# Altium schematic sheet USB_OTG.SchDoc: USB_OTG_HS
size A4; DocumentNumber: MB1165; Revision: C.1; SheetNumber: 8; SheetTotal: 17; Project: STM32469I-EVAL
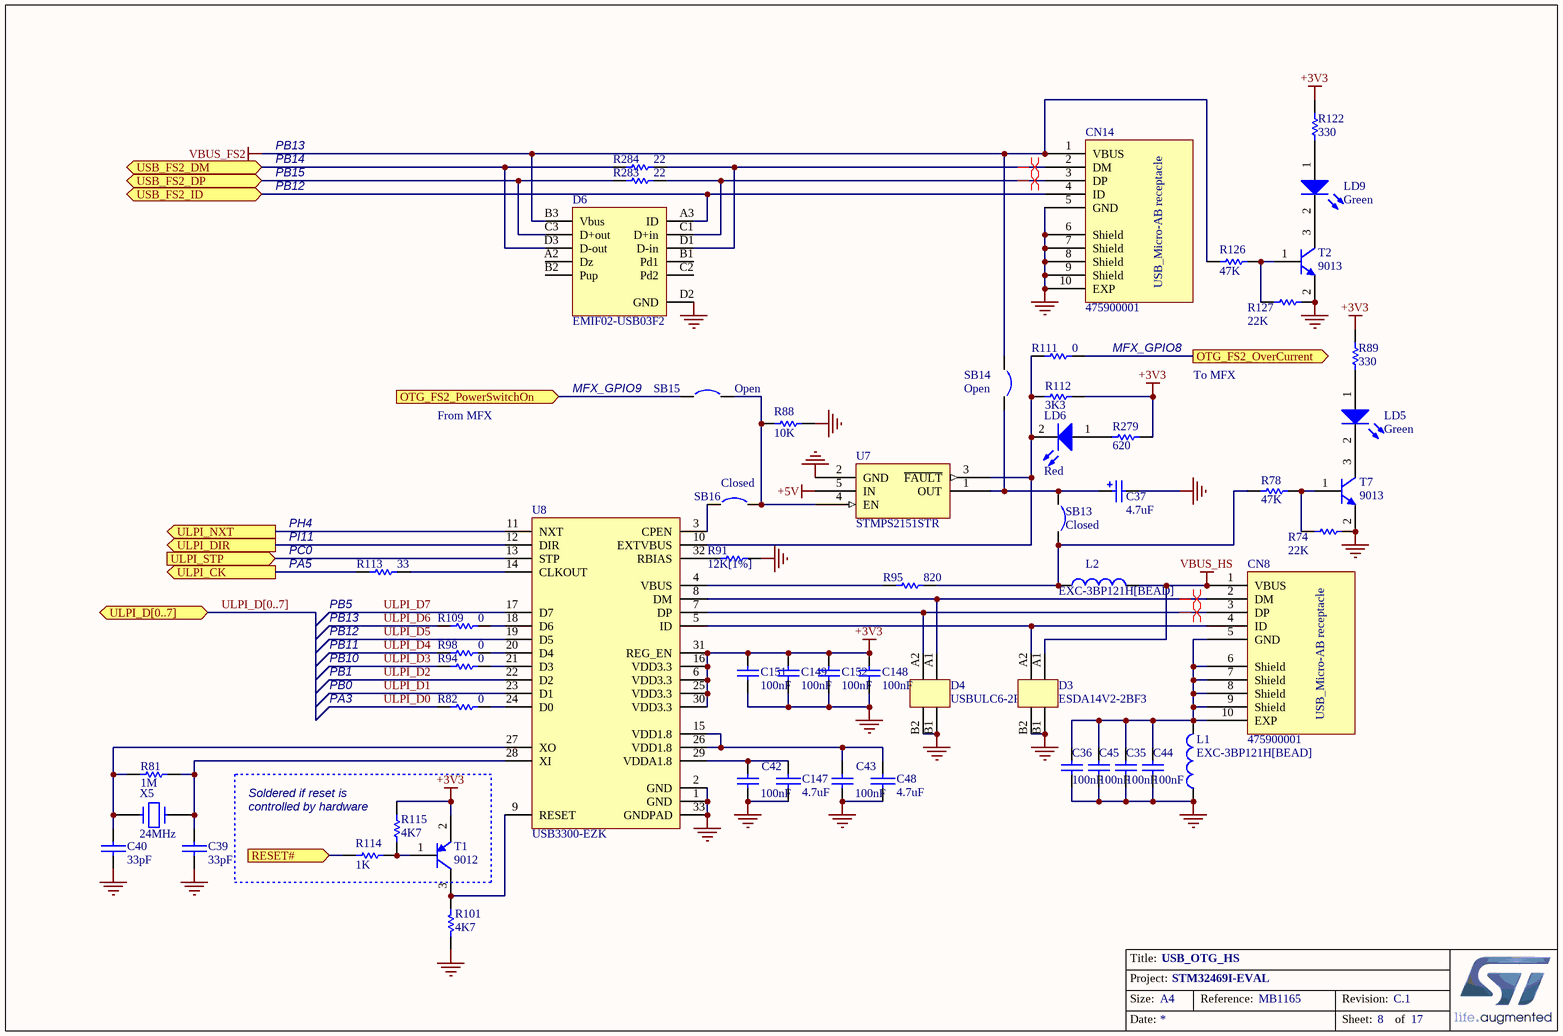
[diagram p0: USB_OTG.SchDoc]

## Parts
C35  100nF  [0603C]
C36  100nF  [0603C]
C37  4.7uF  [TAN-A]
C39  33pF  [0603C]
C40  33pF  [0603C]
C42  100nF  [0603C]
C43  100nF  [0603C]
C44  100nF  [0603C]
C45  100nF  [0603C]
C48  4.7uF  [TAN-A]
C147  4.7uF  [TAN-A]
C148  100nF  [0603C]
C149  100nF  [0603C]
C151  100nF  [0603C]
C152  100nF  [0603C]
CN8  475900001  [MOLEX_47590001]
CN14  475900001  [MOLEX_47590001]
D3  ESDA14V2-2BF3  [BGA4_0R4_0R8X0R8]
D4  USBULC6-2F3  [BGA4_0R4_1X1]
D6  EMIF02-USB03F2  [BGA11_0R5_1R57X2R07]
L1  EXC-3BP121H[BEAD]  [0603L]
L2  EXC-3BP121H[BEAD]  [0603L]
LD5  Green  [0603D]
LD6  Red  [0603D]
LD9  Green  [0603D]
R74  22K  [0603R]
R78  47K  [0603R]
R81  1M  [0603R]
R82  0  [0603R]
R88  10K  [0603R]
R89  330  [0603R]
R91  12K[1%]  [0603R]
R94  0  [0603R]
R95  820  [0603R]
R98  0  [0603R]
R101  4K7  [0603R]
R109  0  [0603R]
R111  0  [0603R]
R112  3K3  [0603R]
R113  33  [0603R]
R114  1K  [0603R]
R115  4K7  [0603R]
R122  330  [0603R]
R126  47K  [0603R]
R127  22K  [0603R]
R279  620  [0603R]
R283  22  [0603R]
R284  22  [0603R]
SB13  Closed  [SB_0603]
SB14  Open  [SB_0603]
SB15  Open  [SB_0603]
SB16  Closed  [SB_0603]
T1  9012  [SOT-23]
T2  9013  [SOT-23]
T7  9013  [SOT-23]
U7  STMPS2151STR  [SOT23-5]
U8  USB3300-EZK  [QFN32_0R5_5X5]
X5  24MHz  [XTAL1]

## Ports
OTG_FS2_OverCurrent (out), OTG_FS2_PowerSwitchOn (in), RESET# (in), ULPI_CK (out), ULPI_D[0..7] (bidir), ULPI_DIR (out), ULPI_NXT (out), ULPI_STP (in), USB_FS2_DM (bidir), USB_FS2_DP (bidir), USB_FS2_ID (bidir)

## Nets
+3V3: C148.1 C149.1 C151.1 C152.1 R89.2 R112.1 R115.1 R122.2 R279.2 T1.2(E) U8.6(VDD3.3) U8.16(VDD3.3) U8.25(VDD3.3) U8.30(VDD3.3) U8.31(REG_EN)
+5V: U7.5(IN)
GND: C35.2 C36.2 C37.2 C39.2 C40.2 C42.2 C43.2 C44.2 C45.2 C48.2 C147.2 C148.2 C149.2 C151.2 C152.2 CN14.5(GND) CN14.6(Shield) CN14.7(Shield) CN14.8(Shield) CN14.9(Shield) CN14.10(EXP) D3.B1 D3.B2 D4.B1 D4.B2 D6.D2(GND) L1.1 R74.1 R88.1 R91.1 R101.1 R127.1 T2.2(E) T7.2(E) U7.2(GND) U8.1(GND) U8.2(GND) U8.33(GNDPAD)
VBUS_FS2: CN14.1(VBUS) D6.B3(Vbus) R126.1 SB14.1
VBUS_HS: CN8.1(VBUS) D3.A1 L2.2
OTG_FS2_OverCurrent: R111.1 ; port OTG_FS2_OverCurrent
OTG_FS2_PowerSwitchOn: SB15.1 ; port OTG_FS2_PowerSwitchOn
RESET#: R114.2 ; port RESET#
ULPI_CK: R113.2 ; port ULPI_CK
ULPI_D0: R82.2
ULPI_D1: U8.23(D1)
ULPI_D2: U8.22(D2)
ULPI_D3: R94.2
ULPI_D4: R98.2
ULPI_D5: U8.19(D5)
ULPI_D6: R109.2
ULPI_D7: U8.17(D7)
ULPI_DIR: U8.12(DIR) ; port ULPI_DIR
ULPI_NXT: U8.11(NXT) ; port ULPI_NXT
ULPI_STP: U8.13(STP) ; port ULPI_STP
USB_FS2_DM: D6.D3(D-out) R284.2 ; port USB_FS2_DM
USB_FS2_DP: D6.C3(D+out) R283.2 ; port USB_FS2_DP
USB_FS2_ID: CN14.4(ID) D6.A3(ID) ; port USB_FS2_ID
NetC35_1: C35.1 C36.1 C44.1 C45.1 CN8.5(GND) CN8.6(Shield) CN8.7(Shield) CN8.8(Shield) CN8.9(Shield) CN8.10(EXP) L1.2
NetC37_1: C37.1 SB13.1 SB14.2 U7.1(OUT)
NetC39_1: C39.1 R81.2 U8.28(XI) X5.1
NetC40_1: C40.1 R81.1 U8.27(XO) X5.2
NetC42_1: C42.1 C147.1 U8.29(VDDA1.8)
NetC43_1: C43.1 C48.1 U8.15(VDD1.8) U8.26(VDD1.8)
NetCN8_2: CN8.2(DM) D4.A1 U8.8(DM)
NetCN8_3: CN8.3(DP) D4.A2 U8.7(DP)
NetCN8_4: CN8.4(ID) D3.A2 U8.5(ID)
NetCN14_2: CN14.2(DM) D6.D1(D-in) R284.1
NetCN14_3: CN14.3(DP) D6.C1(D+in) R283.1
NetL2_1: L2.1 R78.2 R95.2 SB13.2
NetLD5_1: LD5.1(A) R89.1
NetLD5_2: LD5.2(K) T7.3(C)
NetLD6_1: LD6.1(A) R279.1
NetLD6_2: LD6.2(K) R111.2 R112.2 U7.3(~{FAULT}) U8.10(EXTVBUS)
NetLD9_1: LD9.1(A) R122.1
NetLD9_2: LD9.2(K) T2.3(C)
NetR74_2: R74.2 R78.1 T7.1(B)
NetR82_1: R82.1 U8.24(D0)
NetR88_2: R88.2 SB15.2 SB16.2 U7.4(EN)
NetR91_2: R91.2 U8.32(RBIAS)
NetR94_1: R94.1 U8.21(D3)
NetR95_1: R95.1 U8.4(VBUS)
NetR98_1: R98.1 U8.20(D4)
NetR101_2: R101.2 T1.3(C) U8.9(RESET)
NetR109_1: R109.1 U8.18(D6)
NetR113_1: R113.1 U8.14(CLKOUT)
NetR114_1: R114.1 R115.2 T1.1(B)
NetR126_2: R126.2 R127.2 T2.1(B)
NetSB16_1: SB16.1 U8.3(CPEN)

Not connected (* = marked no-connect by the designer): D6 A2(Dz) B1(Pd1) B2(Pup) C2(Pd2)

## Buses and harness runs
bus ULPI_D[0..7] = port ULPI_D[0..7]

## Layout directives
differential pair: NetCN8_2, NetCN8_3, NetCN14_2, NetCN14_3

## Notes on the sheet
- PB13
- PB14
- PB15
- PB12
- MFX_GPIO8
- To MFX
- From MFX
- MFX_GPIO9
- PH4
- PI11
- PC0
- PA5
- PB11
- (near R113) PB13
- (near R113) PB5
- PA3
- PB0
- PB1
- PB10
- (near R115) Soldered if reset is
- (near R115) controlled by hardware

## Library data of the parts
C35 C36 C42-C45 C148 C149 C151 C152 = Cap: Capacitor; Value: 10nF
C37 = Cap Pol1: Polarized Capacitor (Radial); Value: 47uF
C39 C40 C48 C147 = CAP: Capacitor
L1 L2 = Inductor: Value: 100uH
LD5 LD6 LD9 = LED2: Typical RED, GREEN, YELLOW, AMBER GaAs LED
R74 R78 R88 R89 R95 R112 R122 R126 R127 = res1: Resistor; Value: 1K
R81 R82 R91 R94 R98 R101 R109 R111 R113 R115 R279 R283 R284 = Res1: Resistor; Value: 1K
R114 = Res1: Resistor
SB13 SB16 = Circuit Breaker_close: Circuit Breaker
SB14 SB15 = Circuit Breaker
T1 = PNP: PNP Bipolar Transistor
T2 T7 = NPN: NPN Bipolar Transistor; Code - JEDEC: TO-226-AA
U7 = STMPS2141STR
X5 = CRYSTAL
